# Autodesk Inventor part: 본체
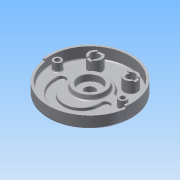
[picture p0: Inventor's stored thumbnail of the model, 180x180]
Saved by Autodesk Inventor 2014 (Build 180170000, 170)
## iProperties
Created: 2015-07
Part Number: 본체
Material: 알루미늄 6061
Document SubType Name: Modeling
Designer: Administrator
Density: 2.71 g/cm^3
Appearance: 알루미늄 - 평지
Mass: 1076.65 g
Surface Area: 1045.77 cm^2
Volume: 397.289 cm^3
Author: Administrator
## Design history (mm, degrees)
sketch "스케치1"
  geometry: C1 r 95 at (0, 0); 1 further point
  constraints: 1 centre point, 1 coincident
  dimensions: "d0" = 190 diameter of C1
extrude "돌출1" new body sketch "스케치1" distance "d1" = 32; taper "d2" = 0 deg
sketch "스케치2"
  geometry: C1 r 95 at (0, 0) reference; C2 r 90 at (0, 0)
  constraints: 1 centre point, 1 coincident
  dimensions: "d3" = 180 diameter of C2
extrude "돌출2" cut sketch "스케치2" distance "d4" = 18; taper "d5" = 0 deg
sketch "스케치3"
  geometry: L1 (0, 0)-(-94.075, -13.221); L2 (0, 0)-(94.075, -13.221); L3 (0, 0)-(0, -95); C1 r 90 at (0, 0) reference; A1 r 95 centre (0, 0) between (-94.075, -13.221) and (94.075, -13.221) reference
  constraints: 6 end point, 3 point on circle, 1 vertical
  dimensions: "d6" = 82 deg angle of L3 L1; "d7" = 82 deg angle of L3 L2
extrude "돌출3" cut sketch "스케치3" distance "d8" = 5; taper "d9" = 0 deg
sketch "스케치4"
  geometry: C1 r 90 at (0, 0) reference; C2 r 35 at (0, 0)
  constraints: 1 centre point, 1 coincident
  dimensions: "d10" = 70 diameter of C2
extrude "돌출4" join sketch "스케치4" distance "d11" = 10; taper "d12" = -10 deg
sketch "스케치5"
  geometry: C1 r 95 at (0, 0) reference; C2 r 26 at (0, 0)
  constraints: 1 centre point, 1 coincident
  dimensions: "d13" = 52 diameter of C2
extrude "돌출5" join sketch "스케치5" distance "d14" = 12; taper "d15" = -15 deg
sketch "스케치6"
  geometry: L1 (-38.833, 16)-(-88.566, 16); L2 (38.833, 16)-(88.566, 16); C1 r 35 at (0, 0) reference; A1 r 90 centre (0, 0) between (-89.124, -12.526) and (89.124, -12.526) reference; A2 r 90 centre (0, 0) between (89.124, -12.526) and (-89.124, -12.526) reference; A3 r 42 centre (0, 0) between (-38.833, 16) and (38.833, 16)
  constraints: 6 point on circle, 4 end point, 1 centre point, 1 coincident, 1 collinear, 1 horizontal
  dimensions: "d16" = 84 diameter of A3; "d17" = 16 distance from line of C1.centre L1
extrude "돌출6" cut sketch "스케치6" distance "d18" = 7; taper "d19" = 0 deg
fillet "모깎기1" dims "d20" = 10
sketch "스케치7"
  geometry: L1 (75.657, 16)-(45.033, 16) reference; L2 (-59, -19)-(59, -19); L3 (-59, -19)-(-59, -14); L4 (-41, -19)-(-41, -14); L5 (41, -19)-(41, -14); L6 (59, -19)-(59, -14); A1 r 90 centre (0, 0) between (-85.114, 29.25) and (85.114, 29.25) reference; A2 r 59 centre (0, -19) between (-59, -19) and (59, -19); A3 r 41 centre (0, -19) between (-41, -19) and (41, -19); A4 r 9 centre (-50, -14) between (-41, -14) and (-59, -14); A5 r 9 centre (50, -14) between (59, -14) and (41, -14)
  constraints: 10 end point, 8 point on circle, 8 tangent, 7 parallel, 4 centre point, 2 point on line, 1 coincident, 1 midpoint, 1 perpendicular, 1 vertical alignment
  dimensions: "d21" = 118 diameter of A2; "d22" = 19 distance of A2.centre A1.centre; "d23" = 41 radius of A3; "d24" = 5 distance of L2.start L3.end
extrude "돌출7" cut sketch "스케치7" distance "d25" = 7; taper "d26" = 0 deg
fillet "모깎기2" dims "d27" = 1
sketch "스케치8"
  geometry: C1 r 9 at (-74, 0); C2 r 9 at (74, 0); A1 r 90 centre (0, 0) between (-85.114, 29.25) and (85.114, 29.25) reference
  constraints: 2 centre point, 2 horizontal alignment, 1 equal radius
  dimensions: "d28" = 18 diameter of C1; "d29" = 148 distance of C2.centre C1.centre; "d30" = 74 distance of C1.centre A1.centre
extrude "돌출8" join sketch "스케치8" stored distance "d31" = 7; taper "d32" = 0 deg
sketch "스케치9"
  geometry: C1 r 15 at (-40, 52); C2 r 15 at (40, 52); A1 r 42 centre (0, 0) between (36.373, 21) and (-36.373, 21) reference
  constraints: 2 centre point, 1 equal radius, 1 horizontal alignment
  dimensions: "d33" = 30 diameter of C1; "d34" = 52 vertical distance of A1.centre C1.centre; "d35" = 80 distance of C2.centre C1.centre; "d36" = 40 horizontal distance of A1.centre C2.centre
extrude "돌출9" join sketch "스케치9" stored distance "d37" = 7; taper "d38" = 0 deg
sketch "스케치10"
  geometry: C1 r 15 at (0, 0) reference; C2 r 15 at (80, 0) reference; 3 further points
  constraints: 2 coincident
hole "구멍1" sketch "스케치10" at (0, 0), (80, 0) diameter "d39" = 20; stored, may be unused: countersink angle "d43" = 90 deg, drill point angle "d45" = 118 deg; dims "d40" = 6, "d41" = 4, "d42" = 2, "d44" = 8
sketch "스케치11"
  geometry: L1 (-6, 13.748)-(-6, -13.748); L2 (6, 13.748)-(6, -13.748); L3 (66.252, 6)-(93.748, 6); L4 (66.252, -6)-(93.748, -6); C1 r 10 at (0, 0) reference; C2 r 10 at (80, 0) reference; A1 r 15 centre (0, 0) between (-6, 13.748) and (-6, -13.748) reference; A2 r 15 centre (80, 0) between (66.252, 6) and (93.748, 6) reference; 1 further point
  constraints: 8 end point, 8 point on circle, 4 parallel, 1 perpendicular, 1 vertical
  dimensions: "d46" = 12 distance between parallel lines of L1 L2; "d47" = 12 distance between parallel lines of L4 L3
extrude "돌출10" cut sketch "스케치11" distance "d48" = 3; taper "d49" = 0 deg
sketch "스케치12"
  geometry: C1 r 9 at (-74, 0) reference; C2 r 9 at (74, 0) reference; 2 further points
  constraints: 2 coincident
hole "구멍2" sketch "스케치12" at (-74, 0), (74, 0) diameter "d50" = 11; stored, may be unused: countersink angle "d54" = 90 deg, drill point angle "d56" = 118 deg; dims "d51" = 6, "d52" = 18, "d53" = 11, "d55" = 8
sketch "스케치13"
  geometry: C1 r 95 at (0, 0) reference; C2 r 68 at (0, 0)
  constraints: 1 centre point, 1 coincident, 1 other
  dimensions: "d57" = 136 diameter of C2
feature "엠보싱1" sketch "스케치13" dims "d58" = 0.5, "d59" = 0
sketch "스케치14"
  geometry: C1 r 33.237 at (0, 0) reference; 1 further point
  constraints: 1 coincident
hole "구멍3" sketch "스케치14" at (0, 0) diameter "d60" = 23; stored, may be unused: countersink angle "d64" = 90 deg, drill point angle "d66" = 118 deg; dims "d61" = 6, "d62" = 50, "d63" = 15, "d65" = 8
chamfer "모따기1" distance "d67" = 1; stored, may be unused: second distance "d68" = 2, angle "d69" = 45 deg
fillet "모깎기3" dims "d70" = 0.3
fillet "모깎기4" dims "d71" = 3, "d72" = 5
node "솔리드1"
node "투영된 루프1"
